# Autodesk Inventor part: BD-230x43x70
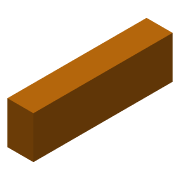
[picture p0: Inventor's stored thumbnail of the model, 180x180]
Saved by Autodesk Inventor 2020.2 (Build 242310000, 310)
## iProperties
Created: 2015-11
Part Number: BD-230x43x70
Material: Ogólny
Document SubType Name: Modeling
Designer: F.Stasiak
Density: 1 g/cm^3
Appearance: Pomarańczowa
Catalog Web Link: www.expertbooks.pl
Manager: www.cadconsulting.pl
Company: Fabian Stasiak CAD Consulting
Author: F.Stasiak
Subject: Zbiór ćwiczeń. Autodesk Inventor 2020. Kurs Professional
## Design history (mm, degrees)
sketch "Szkic1"
  geometry: L1 (-21.5, 115)-(21.5, 115); L2 (21.5, 115)-(21.5, -115); L3 (21.5, -115)-(-21.5, -115); L4 (-21.5, -115)-(-21.5, 115); L5 (-21.5, 115)-(21.5, -115); L6 (21.5, 115)-(-21.5, -115); 1 further point
  constraints: 12 end point, 2 midpoint, 2 parallel, 1 horizontal, 1 perpendicular
  dimensions: "d0" = 43 distance of L2.end L3.end; "d1" = 230 distance of L1.end L2.end
extrude "Wyciągnięcie proste1" new body sketch "Szkic1" distance "d2" = 70; taper "d3" = 0 deg
node "Bryła1"
